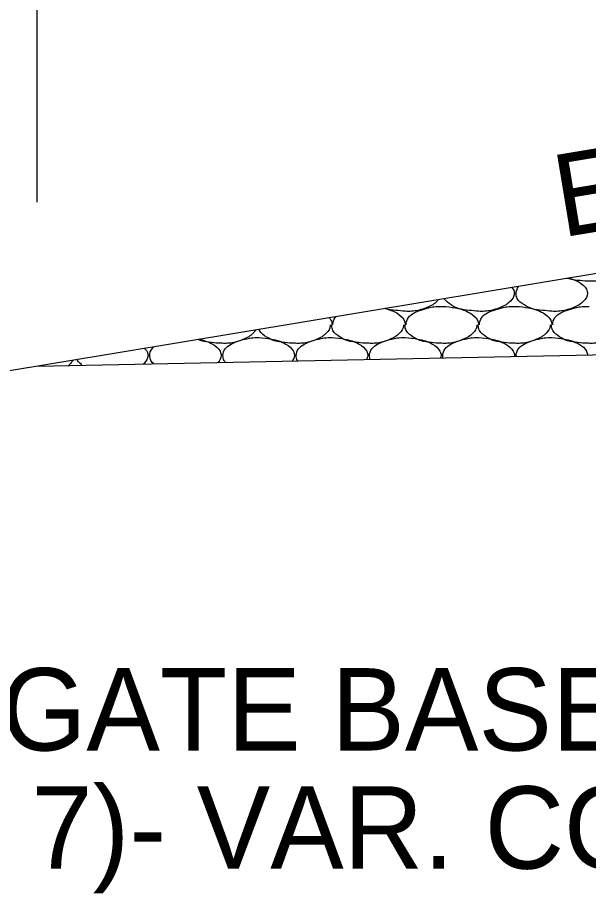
# Model space of a CAD drawing. Extents: x 1364961 to 1365294, y 367927 to 368034.
# Drawn here: x 1365175.36 to 1365179.35, y 367966.75 to 367972.87 of the extents above; entities that cross this region are included whole.
import ezdxf

# ---------------------------------------------------------------- set-up
doc = ezdxf.new("R2010")
doc.units = 0
doc.layers.add('Default', color=7, linetype='Continuous')

msp = doc.modelspace()

# ---------------------------------------------------------------- linework, layer by layer
at = {"layer": 'Default'}
for p, q in [((1365175.4981, 367971.581), (1365175.4981, 367988.923)), ((1365187.4981, 367972.4254), (1365166.1432, 367968.8787)), ((1365178.3261, 367970.8514), (1365178.3321, 367970.8514)), ((1365178.8381, 367970.8514), (1365178.8441, 367970.8514)), ((1365179.3501, 367970.8514), (1365179.3561, 367970.8514)), ((1365193.4821, 367970.7914), (1365175.4981, 367970.4324))]:
    msp.add_line(p, q, dxfattribs=at)
for points in [[(1365179.5761, 367971.1094), (1365179.5661, 367971.0974), (1365179.5361, 367971.0734), (1365179.4741, 367971.0454), (1365179.3881, 367971.0274), (1365179.3501, 367971.0274)], [(1365179.2141, 367971.0494), (1365179.2841, 367971.0214), (1365179.3361, 367970.9714), (1365179.3441, 367970.9414), (1365179.3161, 367970.8874), (1365179.2861, 367970.8634), (1365179.2241, 367970.8354), (1365179.1381, 367970.8174), (1365179.0941, 367970.8174), (1365179.0281, 367970.8234), (1365178.9561, 367970.8354), (1365178.9021, 367970.8614), (1365178.8521, 367970.9074), (1365178.8441, 367970.9414), (1365178.8601, 367970.9894), (1365178.8611, 367970.9914)], [(1365179.3501, 367971.0274), (1365179.3421, 367971.0274), (1365179.2761, 367971.0334), (1365179.2041, 367971.0454), (1365179.1981, 367971.0474)], [(1365178.8151, 367970.9834), (1365178.8241, 367970.9714), (1365178.8321, 367970.9414), (1365178.8041, 367970.8874), (1365178.7741, 367970.8634), (1365178.7121, 367970.8354), (1365178.6261, 367970.8174), (1365178.5821, 367970.8174), (1365178.5161, 367970.8234), (1365178.4441, 367970.8354), (1365178.3901, 367970.8614), (1365178.3421, 367970.9044)], [(1365178.3001, 367970.8974), (1365178.2921, 367970.8874), (1365178.2621, 367970.8634), (1365178.2001, 367970.8354), (1365178.1141, 367970.8174), (1365178.0701, 367970.8174), (1365178.0041, 367970.8234), (1365177.9321, 367970.8354), (1365177.9291, 367970.8364)], [(1365177.9301, 367970.8364), (1365178.0101, 367970.8054), (1365178.0621, 367970.7554), (1365178.0701, 367970.7254), (1365178.0701, 367970.7234)], [(1365178.0761, 367970.7234), (1365178.0761, 367970.7254), (1365178.0921, 367970.7734), (1365178.1321, 367970.8054), (1365178.1721, 367970.8234), (1365178.2321, 367970.8414), (1365178.2701, 367970.8494), (1365178.3261, 367970.8514)], [(1365178.3321, 367970.8514), (1365178.4201, 367970.8414), (1365178.5221, 367970.8054), (1365178.5741, 367970.7554), (1365178.5821, 367970.7254), (1365178.5821, 367970.7234)], [(1365178.5881, 367970.7234), (1365178.5881, 367970.7254), (1365178.6041, 367970.7734), (1365178.6441, 367970.8054), (1365178.6841, 367970.8234), (1365178.7441, 367970.8414), (1365178.7821, 367970.8494), (1365178.8381, 367970.8514)], [(1365178.8441, 367970.8514), (1365178.9321, 367970.8414), (1365179.0341, 367970.8054), (1365179.0861, 367970.7554), (1365179.0941, 367970.7254), (1365179.0941, 367970.7234)], [(1365179.1001, 367970.7234), (1365179.1001, 367970.7254), (1365179.1161, 367970.7734), (1365179.1561, 367970.8054), (1365179.1961, 367970.8234), (1365179.2561, 367970.8414), (1365179.2941, 367970.8494), (1365179.3501, 367970.8514)], [(1365177.5401, 367970.7714), (1365177.5501, 367970.7554), (1365177.5581, 367970.7254), (1365177.5581, 367970.7234)], [(1365177.5641, 367970.7234), (1365177.5641, 367970.7254), (1365177.5801, 367970.7734), (1365177.5841, 367970.7794)], [(1365177.5461, 367970.7234), (1365177.5461, 367970.7174), (1365177.5181, 367970.6634), (1365177.4881, 367970.6394), (1365177.4261, 367970.6114), (1365177.3401, 367970.5934), (1365177.3021, 367970.5934)], [(1365177.8141, 367970.5934), (1365177.8061, 367970.5934), (1365177.7401, 367970.5994), (1365177.6681, 367970.6114), (1365177.6141, 367970.6374), (1365177.5641, 367970.6834), (1365177.5561, 367970.7174), (1365177.5561, 367970.7234)], [(1365178.0581, 367970.7234), (1365178.0581, 367970.7174), (1365178.0301, 367970.6634), (1365178.0001, 367970.6394), (1365177.9381, 367970.6114), (1365177.8521, 367970.5934), (1365177.8141, 367970.5934)], [(1365178.3261, 367970.5934), (1365178.3181, 367970.5934), (1365178.2521, 367970.5994), (1365178.1801, 367970.6114), (1365178.1261, 367970.6374), (1365178.0761, 367970.6834), (1365178.0681, 367970.7174), (1365178.0681, 367970.7234)], [(1365178.5701, 367970.7234), (1365178.5701, 367970.7174), (1365178.5421, 367970.6634), (1365178.5121, 367970.6394), (1365178.4501, 367970.6114), (1365178.3641, 367970.5934), (1365178.3261, 367970.5934)], [(1365178.8381, 367970.5934), (1365178.8301, 367970.5934), (1365178.7641, 367970.5994), (1365178.6921, 367970.6114), (1365178.6381, 367970.6374), (1365178.5881, 367970.6834), (1365178.5801, 367970.7174), (1365178.5801, 367970.7234)], [(1365179.0821, 367970.7234), (1365179.0821, 367970.7174), (1365179.0541, 367970.6634), (1365179.0241, 367970.6394), (1365178.9621, 367970.6114), (1365178.8761, 367970.5934), (1365178.8381, 367970.5934)], [(1365179.3501, 367970.5934), (1365179.3421, 367970.5934), (1365179.2761, 367970.5994), (1365179.2041, 367970.6114), (1365179.1501, 367970.6374), (1365179.1001, 367970.6834), (1365179.0921, 367970.7174), (1365179.0921, 367970.7234)], [(1365179.5941, 367970.7234), (1365179.5941, 367970.7174), (1365179.5661, 367970.6634), (1365179.5361, 367970.6394), (1365179.4741, 367970.6114), (1365179.3881, 367970.5934), (1365179.3501, 367970.5934)], [(1365177.0231, 367970.6854), (1365177.0061, 367970.6634), (1365176.9761, 367970.6394), (1365176.9141, 367970.6114), (1365176.8281, 367970.5934), (1365176.7901, 367970.5934)], [(1365176.8151, 367970.4584), (1365176.8041, 367970.4734), (1365176.7961, 367970.5074), (1365176.8121, 367970.5554), (1365176.8521, 367970.5874), (1365176.8921, 367970.6054), (1365176.9521, 367970.6234), (1365176.9901, 367970.6314), (1365177.0461, 367970.6334)], [(1365177.0461, 367970.6334), (1365177.1341, 367970.6234), (1365177.2361, 367970.5874), (1365177.2881, 367970.5374), (1365177.2961, 367970.5074), (1365177.2791, 367970.4684)], [(1365177.3021, 367970.5934), (1365177.2941, 367970.5934), (1365177.2281, 367970.5994), (1365177.1561, 367970.6114), (1365177.1021, 367970.6374), (1365177.0521, 367970.6834), (1365177.0491, 367970.6904)], [(1365177.3191, 367970.4684), (1365177.3161, 367970.4734), (1365177.3081, 367970.5074), (1365177.3241, 367970.5554), (1365177.3641, 367970.5874), (1365177.4041, 367970.6054), (1365177.4641, 367970.6234), (1365177.5021, 367970.6314), (1365177.5581, 367970.6334)], [(1365177.5581, 367970.6334), (1365177.6461, 367970.6234), (1365177.7481, 367970.5874), (1365177.8001, 367970.5374), (1365177.8081, 367970.5074), (1365177.7981, 367970.4784)], [(1365177.8251, 367970.4784), (1365177.8201, 367970.5074), (1365177.8361, 367970.5554), (1365177.8761, 367970.5874), (1365177.9161, 367970.6054), (1365177.9761, 367970.6234), (1365178.0141, 367970.6314), (1365178.0701, 367970.6334)], [(1365178.0701, 367970.6334), (1365178.1581, 367970.6234), (1365178.2601, 367970.5874), (1365178.3121, 367970.5374), (1365178.3201, 367970.5074), (1365178.3141, 367970.4884)], [(1365178.3331, 367970.4894), (1365178.3321, 367970.5074), (1365178.3481, 367970.5554), (1365178.3881, 367970.5874), (1365178.4281, 367970.6054), (1365178.4881, 367970.6234), (1365178.5261, 367970.6314), (1365178.5821, 367970.6334)], [(1365178.5821, 367970.6334), (1365178.6701, 367970.6234), (1365178.7721, 367970.5874), (1365178.8241, 367970.5374), (1365178.8321, 367970.5074), (1365178.8301, 367970.4994)], [(1365178.8441, 367970.4994), (1365178.8441, 367970.5074), (1365178.8601, 367970.5554), (1365178.9001, 367970.5874), (1365178.9401, 367970.6054), (1365179.0001, 367970.6234), (1365179.0381, 367970.6314), (1365179.0941, 367970.6334)], [(1365179.0941, 367970.6334), (1365179.1821, 367970.6234), (1365179.2841, 367970.5874), (1365179.3361, 367970.5374), (1365179.3441, 367970.5094)], [(1365176.7901, 367970.5934), (1365176.7821, 367970.5934), (1365176.7161, 367970.5994), (1365176.6441, 367970.6114), (1365176.6221, 367970.6194)], [(1365176.6331, 367970.6214), (1365176.7241, 367970.5874), (1365176.7761, 367970.5374), (1365176.7841, 367970.5074), (1365176.7601, 367970.4574)], [(1365176.2491, 367970.5574), (1365176.2641, 367970.5374), (1365176.2721, 367970.5074), (1365176.2441, 367970.4534), (1365176.2381, 367970.4474)], [(1365176.3131, 367970.4484), (1365176.2921, 367970.4734), (1365176.2841, 367970.5074), (1365176.3001, 367970.5554), (1365176.3111, 367970.5674)], [(1365175.7471, 367970.4734), (1365175.7321, 367970.4534), (1365175.7141, 367970.4364)], [(1365175.8131, 367970.4384), (1365175.7801, 367970.4734), (1365175.7771, 367970.4784)]]:
    msp.add_spline(points, degree=3, dxfattribs=at)

# ---------------------------------------------------------------- texts
msp.add_text('EXIST. SLOPE', height=0.576, rotation=9.4298, dxfattribs=at).set_placement((1365179.1632, 367971.3326))
for s, p in [('AGGREGATE BASE COURSE', (1365172.4606, 367967.7471)), ("(CLASS 7)- VAR. COMP'D. DEPTH", (1365172.4606, 367966.9211))]:
    msp.add_text(s, height=0.576, dxfattribs=at).set_placement(p)

doc.saveas('drawing.dxf')
